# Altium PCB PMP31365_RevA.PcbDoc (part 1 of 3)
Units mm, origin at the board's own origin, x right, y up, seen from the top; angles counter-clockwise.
Board outline 134.61 x 49.53 mm, 4 copper layers (Top Layer, Layer 1, Layer 2, Bottom Layer), stack 1.787 mm thick; 183 components, 83 nets, 384 pads, 167 vias.
Unrouted connection lines stored in the file: 14.
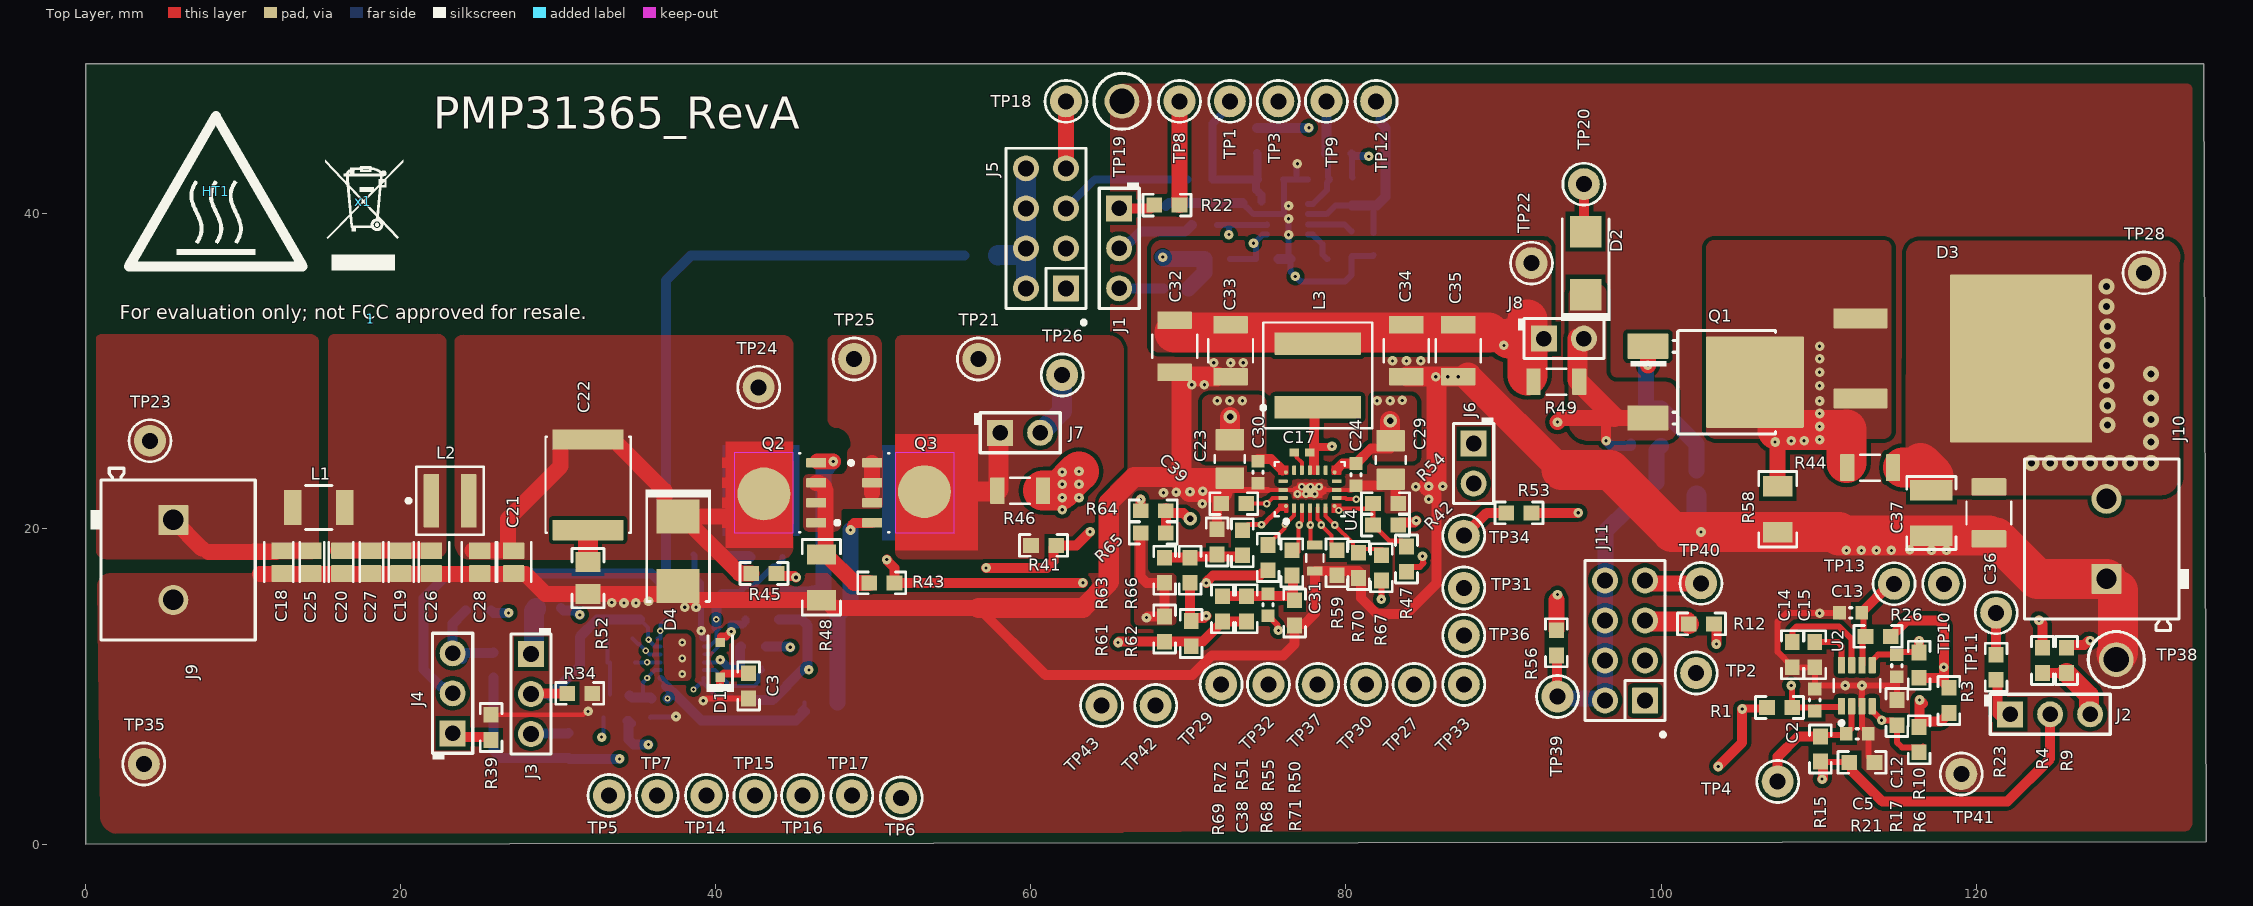
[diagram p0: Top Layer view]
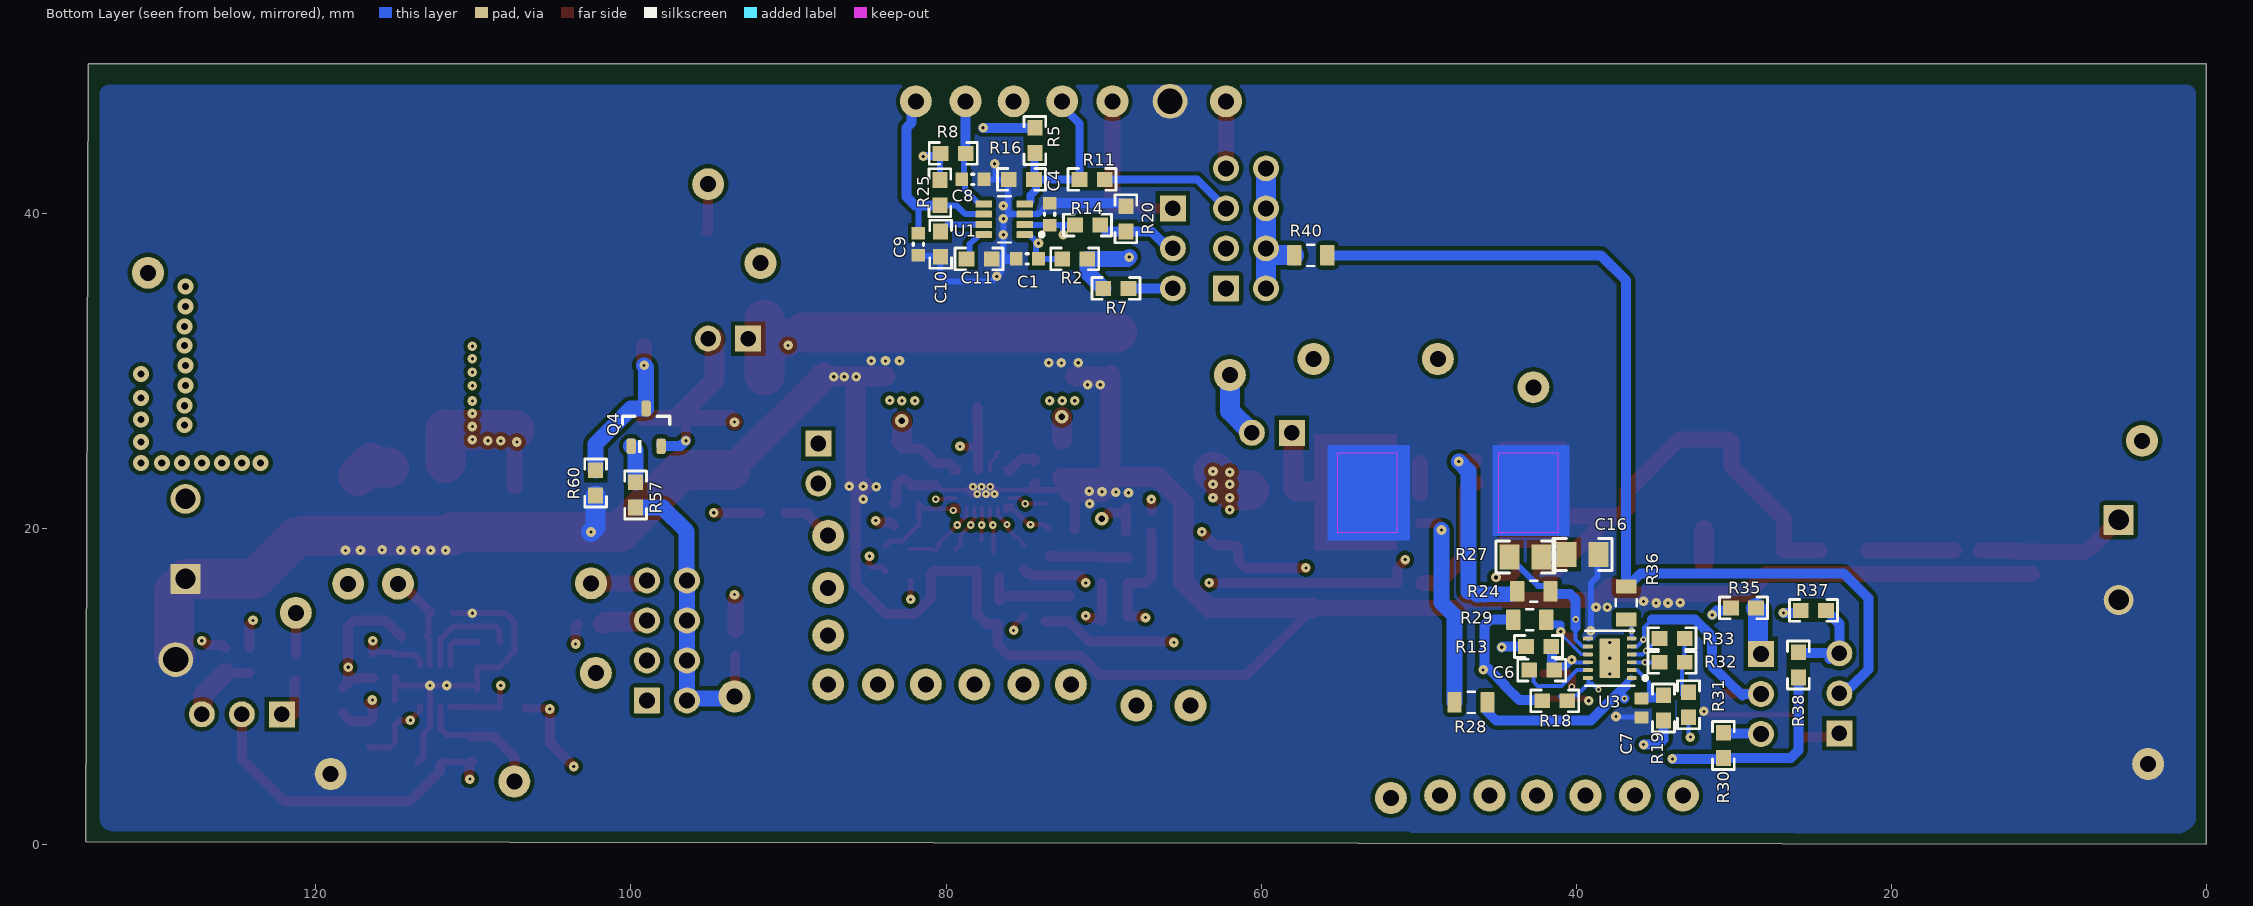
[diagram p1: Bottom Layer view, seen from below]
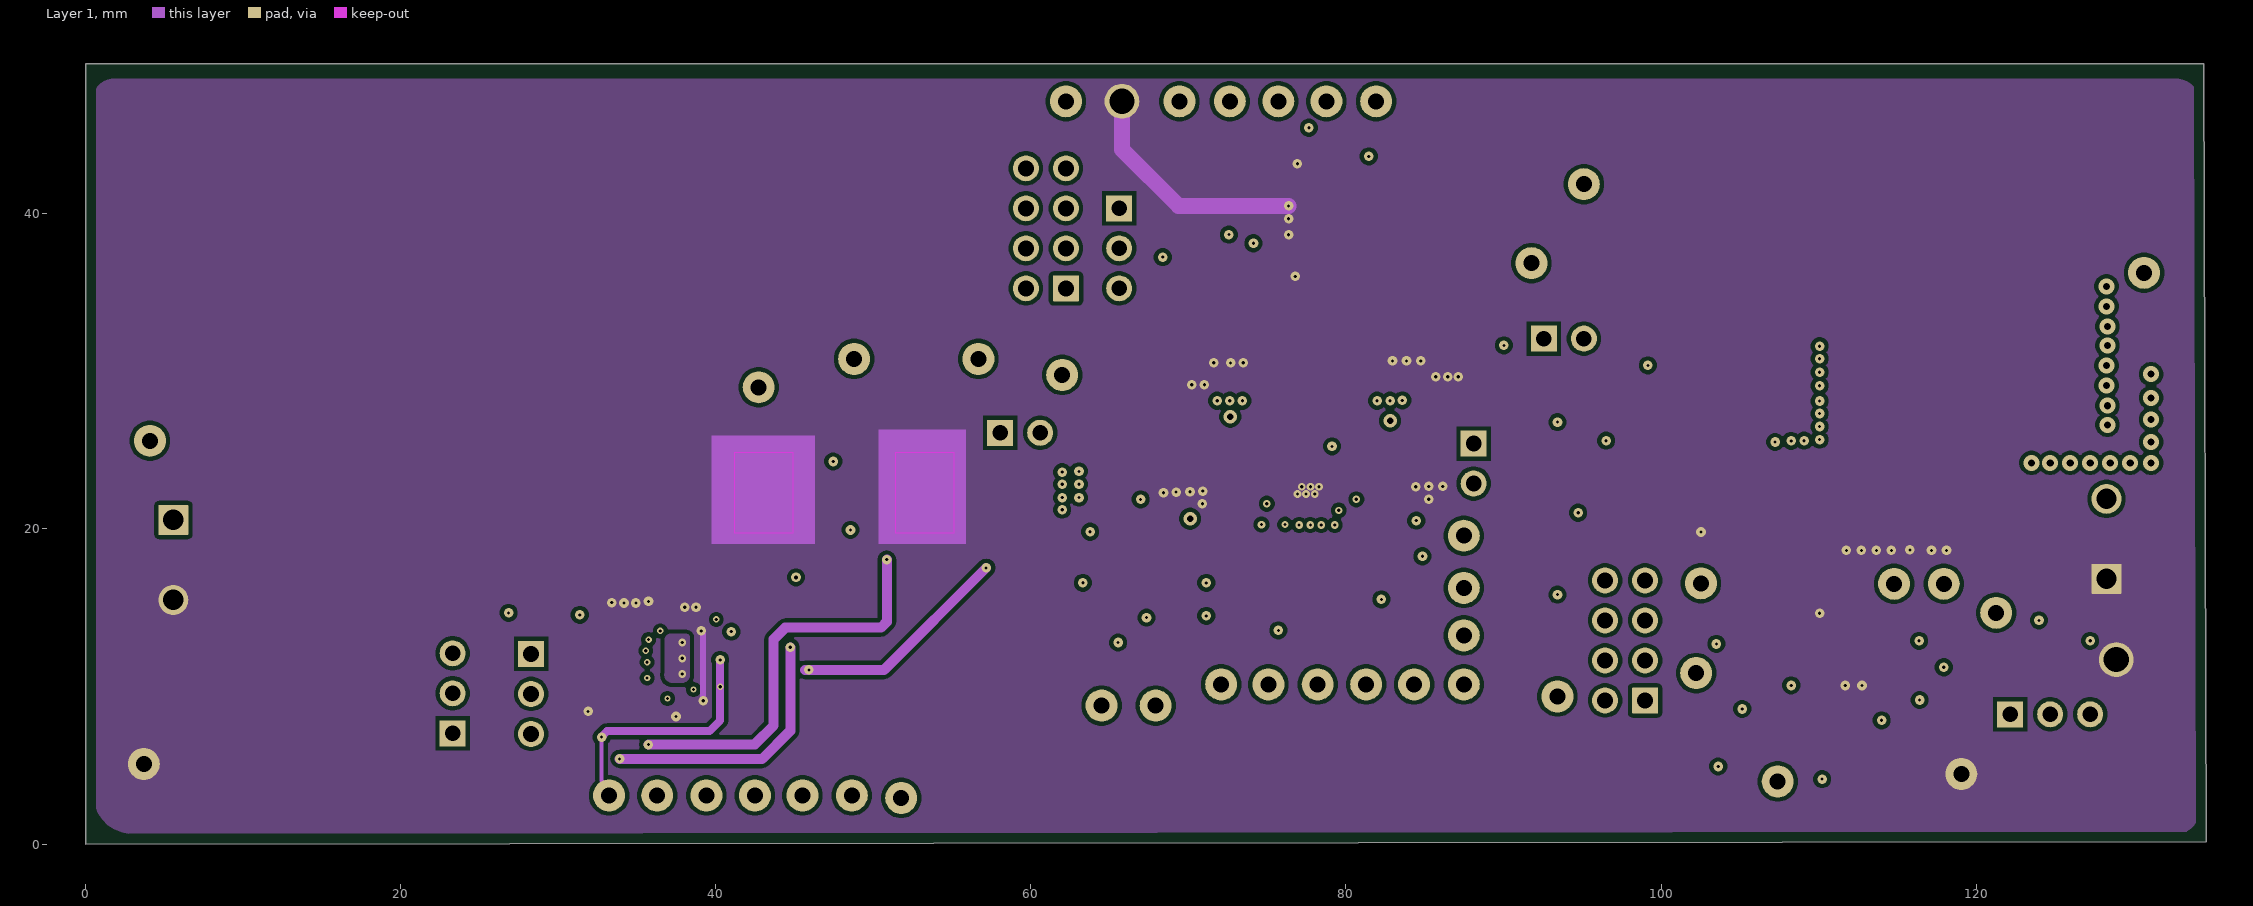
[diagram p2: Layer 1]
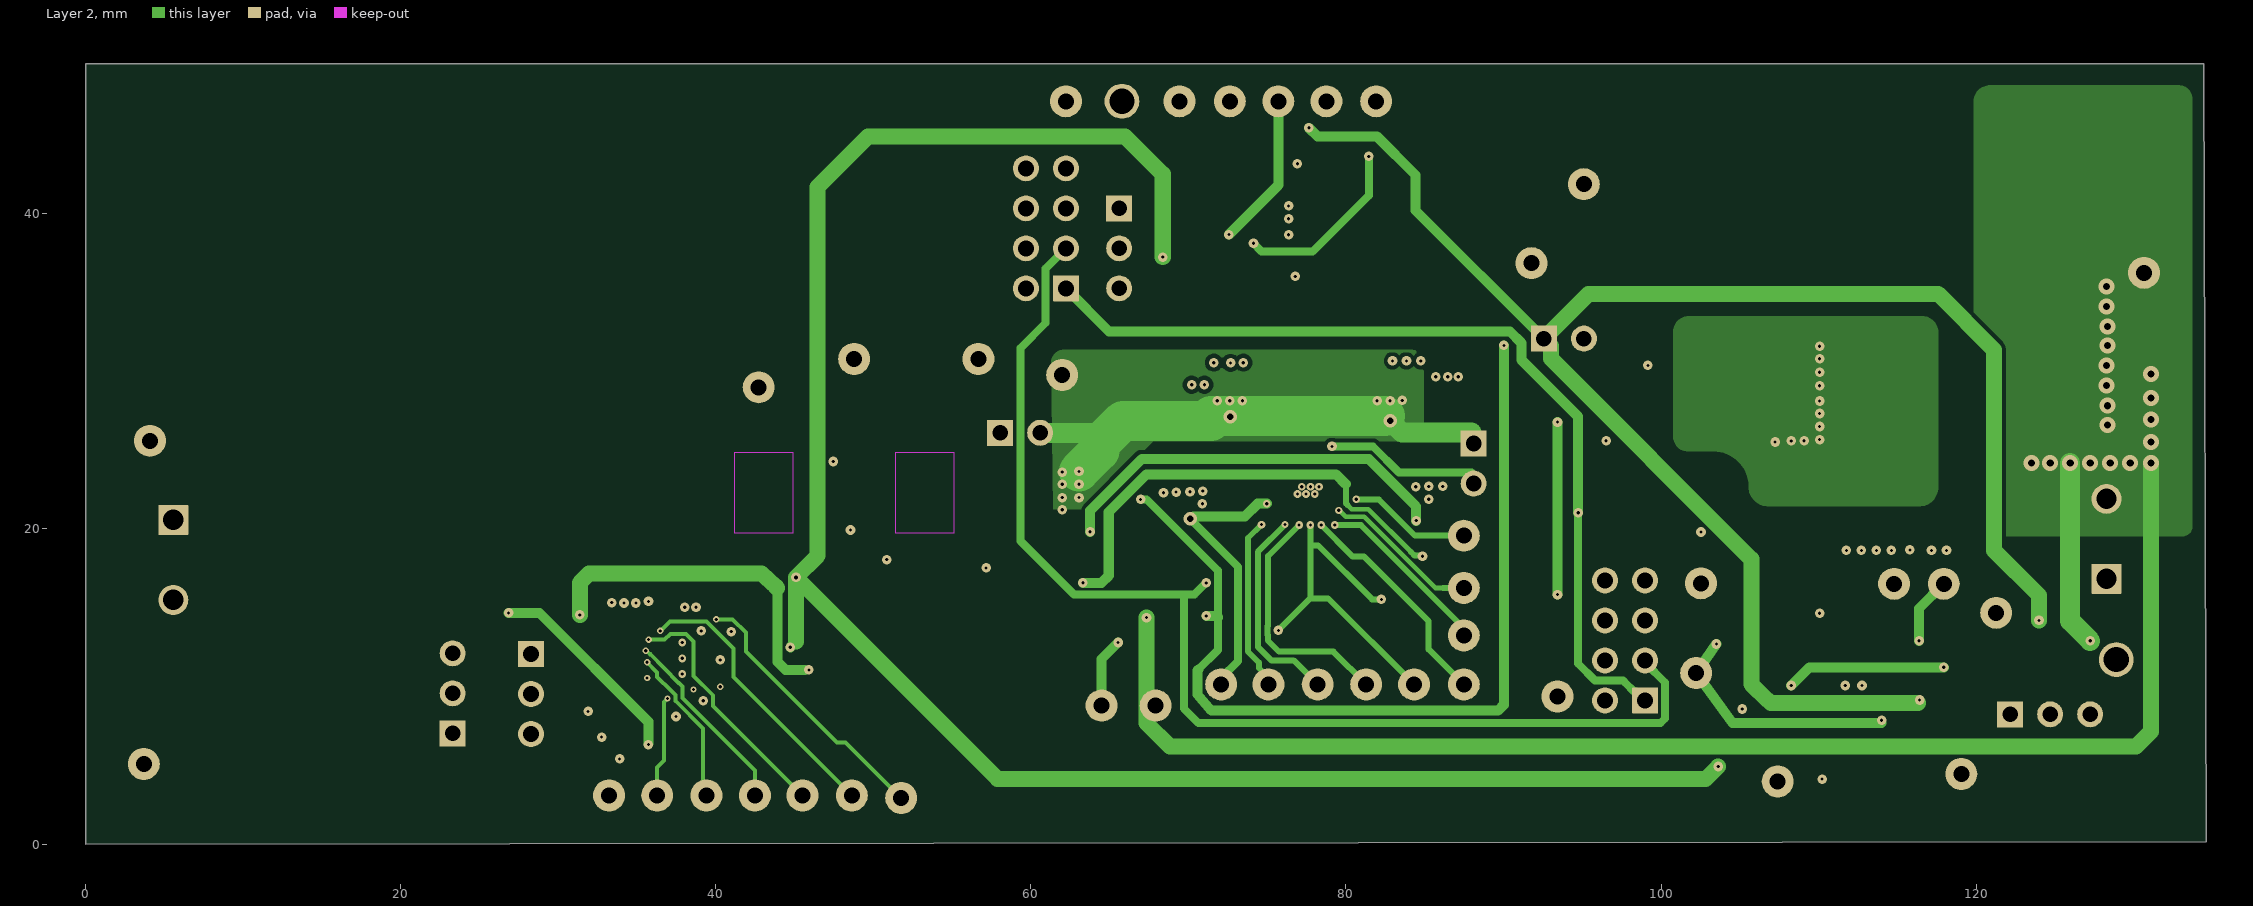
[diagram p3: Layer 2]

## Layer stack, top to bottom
Top Solder: solder mask 0.0102, Solder Resist, Dk 3.5
Top Layer: signal copper 0.0356
Dielectric 1: prepreg 0.0711, PP-006, Dk 4.1
Layer 1: signal copper 0.035
Dielectric1: core 1.5037, FR-4 High Tg, Dk 4.8
Layer 2: signal copper 0.035
Dielectric 2: prepreg 0.0711, PP-006, Dk 4.1
Bottom Layer: signal copper 0.0356
Bottom Solder: solder mask 0.0102, Solder Resist, Dk 3.5

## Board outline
0,0 0,49.53 134.461,49.53 134.611,0.143

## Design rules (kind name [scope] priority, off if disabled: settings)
AcuteAngle [All] p1: minimum=4.50000000000000E+0001 checktracksonly=FALSE
AssemblyTestPointUsage [All] p1: valid=2
BoardOutlineClearance BoardOutlineClearance_MountingHoles [OnCopper and InComponentClass('Mounting Holes')] p1: gap=1 ignorepadtopadclearanceinfootprint=FALSE
BoardOutlineClearance BoardOutlineClearance_Poly [OnCopper and IsPoly] p2: gap=0.635 ignorepadtopadclearanceinfootprint=FALSE
BoardOutlineClearance [OnCopper and Not InComponentClass('Logo') and not InComponentClass('FiducialMark') and not InRegion(1000,500,4000,800) and not InPoly] p3: gap=1.016 ignorepadtopadclearanceinfootprint=FALSE
Clearance Clearance_Keepouts [((IsTrack Or IsArc) And Not InPoly) And IsFree and IsKeepOut vs ((IsTrack Or IsArc) And Not InPoly) And IsFree and IsKeepOut] p1: gap=0 ignorepadtopadclearanceinfootprint=FALSE
Clearance Clearance_Poly [InPolygon] p2: gap=0.254 ignorepadtopadclearanceinfootprint=TRUE
Clearance Clearance_FiducialMark [IsKeepOut and InComponentClass('FiducialMark') vs IsPad and InComponentClass('FiducialMark')] p3: gap=0 ignorepadtopadclearanceinfootprint=FALSE
Clearance [All] p4: gap=0.178 ignorepadtopadclearanceinfootprint=TRUE
ComponentClearance ComponentClearance_MountingHoles_FiducialMarks [InComponentClass('Mounting Holes') vs InComponentClass('FiducialMark')] p1: gap=1.27 collisioncheckmode=3 verticalgap=0.254 showdistances=FALSE
ComponentClearance ComponentClearance_Shunt [InComponentClass('Header') vs InComponentClass('Shunt')] p2: gap=0 collisioncheckmode=3 verticalgap=0 showdistances=FALSE
ComponentClearance ComponentClearance_Logo [InComponentClass('Logo')] p3: gap=0.762 collisioncheckmode=3 verticalgap=0.254 showdistances=FALSE
ComponentClearance ComponentClearance_ScrewToNut [(HasFootprint('NY PMS 440 0025 PH')) vs (HasFootprint('Keystone_1902C'))] p4: gap=0.127 collisioncheckmode=3 verticalgap=0.254 showdistances=FALSE
ComponentClearance ComponentClearance_MountingHoles [InComponentClass('Mounting Holes')] p5: gap=2.54 collisioncheckmode=3 verticalgap=2540 showdistances=FALSE
ComponentClearance ComponentClearance_SmallPassives [HasFootprint('0201*') or HasFootprint('0402*') or HasFootprint('0508') or HasFootprint('0603*') or HasFootprint('0612') or HasFootprint('0805*') or HasFootprint('0815*') or HasFootprint('0830*') or HasFootprint('1206*') or HasFootprint('1210*') or HasFootprint('1808*') or HasFootprint('1812*') or HasFootprint('1825*') or HasFootprint('2010*') or HasFootprint('2220*') or HasFootprint('2225*') or HasFootprint('2512*') or HasFootprint('2728*') or HasFootprint('3518*') vs HasFootprint('0201*') or HasFootprint('0402*') or HasFootprint('0508') or HasFootprint('0603*') or HasFootprint('0612') or HasFootprint('0805*') or HasFootprint('0815*') or HasFootprint('0830*') or HasFootprint('1206*') or HasFootprint('1210*') or HasFootprint('1808*') or HasFootprint('1812*') or HasFootprint('1825*') or HasFootprint('2010*') or HasFootprint('2220*') or HasFootprint('2225*') or HasFootprint('2512*') or HasFootprint('2728*') or HasFootprint('3518*')] p6: gap=0.38 collisioncheckmode=3 verticalgap=0.254 showdistances=FALSE
ComponentClearance ComponentClearance_THtoSMT [IsThruComponent vs IsSMTComponent] p7: gap=0.762 collisioncheckmode=3 verticalgap=0.762 showdistances=FALSE
ComponentClearance ComponentClearance_THtoTH [IsThruComponent vs IsThruComponent] p8: gap=0.508 collisioncheckmode=3 verticalgap=0.762 showdistances=FALSE
ComponentClearance [All] p9: gap=0.508 collisioncheckmode=3 verticalgap=0.254 showdistances=FALSE
DiffPairsRouting [All] p1: maxlimit=2.54 minlimit=0.254 mostfreqgap=0.254 toplayer_minwidth=0.381 toplayer_maxwidth=0.381 toplayer_prefwidth=0.381 midlayer1_minwidth=0.381 midlayer1_maxwidth=0.381 midlayer1_prefwidth=0.381 midlayer2_minwidth=0.381 midlayer2_maxwidth=0.381 midlayer2_prefwidth=0.381 bottomlayer_minwidth=0.381 bottomlayer_maxwidth=0.381 bottomlayer_prefwidth=0.381 maxuncoupledlength=25.4
FabricationTestPointUsage TestPointUsage [All] p1: valid=2 allowmultiple=FALSE
FabricationTestpoint Testpoint [All] p1: side=3 testpointundercomponent=TRUE minsize=1.016 maxsize=2.54 preferedsize=1.524 minholesize=0 maxholesize=1.016 preferedholesize=0.813 testpointgrid=0.025 allowsidetop=TRUE allowsidebottom=TRUE usegrid=TRUE gridtolerance=0
FanoutControl Fanout_LCC [IsLCC] p1: bgadir=Out bgaviamode=Centered fanoutstyle=Auto fanoutdirection=Alternating viagrid=0.025 // Fanout_LCC (Default Rule)
FanoutControl Fanout_BGA [IsBGA] p2: bgadir=Out bgaviamode=Centered fanoutstyle=Auto fanoutdirection=Alternating viagrid=0.025 // Fanout_BGA (Default Rule)
FanoutControl Fanout_Default [All] p4: bgadir=Out bgaviamode=Centered fanoutstyle=Auto fanoutdirection=Alternating viagrid=0.025 // Fanout_Default (Default Rule)
FanoutControl Fanout_Small [(CompPinCount < 5)] p5: bgadir=Out bgaviamode=Centered fanoutstyle=Auto fanoutdirection=OutThenIn viagrid=0.025 // Fanout_Small (Default Rule)
HoleSize [All] p1: absolutevalues=TRUE maxlimit=6.375 minlimit=0.2 maxpercent=80.000 minpercent=20.000
MinimumAnnularRing MinimumAnnularRing_ThermalPadVias [IsVia and InAnyComponent] p1: minimumring=0.15
MinimumAnnularRing [All] p2: minimumring=0.099
MinimumSolderMaskSliver MinimumSolderMaskSliver_Logo [InComponentClass('Logo') vs InComponentClass('Logo')] p1: minsoldermaskwidth=0.018
MinimumSolderMaskSliver [All] p2: minsoldermaskwidth=0.027
PlaneConnect [All] p1: planeconnectstyle=Relief reliefexpansion=0.254 reliefentries=4 reliefconductorwidth=0.254 reliefairgap=0.254
PolygonConnect [All] p1: connectstyle=Direct reliefconductorwidth=0.254 reliefentries=4 polygonreliefangle="90 Angle" airgapwidth=0.254
RoutingVias ThermalPadVias [IsVia and InAnyComponent] p1: holewidth=0.2 width=0.5 viastyle="Through Hole" minholewidth=0.2 minwidth=0.5 maxholewidth=0.33 maxwidth=0.6
RoutingVias [All] p2: holewidth=0.406 width=0.864 viastyle="Through Hole" minholewidth=0.102 minwidth=0.127 maxholewidth=1.016 maxwidth=1.651
SilkToBoardRegionClearance [Not ((IsComment or IsDesignator) And (Hide <> 'False')) and not InRegion(1000,500,4000,800)] p1:
SilkToSilkClearance SilkToSilkClearance_Pb-FreeLogo [(HasFootprint('Pb-Free_Overlay_Medium') OR HasFootprint('Pb-Free_Overlay_Small')) vs (HasFootprint('Pb-Free_Overlay_Medium') OR HasFootprint('Pb-Free_Overlay_Small'))] p1 off: silktosilkclearance=0
SilkToSilkClearance [All] p2 off: silktosilkclearance=0.1
SilkToSolderMaskClearance SilkToComponentPadClearance [(IsPad or IsFill or IsRegion) and InAnycomponent] p1 off: minsilkscreentomaskgap=0.127 clearancetoexposedcopper=TRUE
SilkToSolderMaskClearance "Silk to Solder Mask Opening" [All] p2 off: minsilkscreentomaskgap=0.1 clearancetoexposedcopper=FALSE
SolderMaskExpansion [All] p1: expansion=0.05 istentingtop=FALSE
UnRoutedNet [All] p1: checkbadconnections=TRUE
Width [All] p1: maxlimit=2.54 minlimit=0.152 preferedwidth=0.254 checkconnectedcopper=TRUE
14 further rules are at their usual default settings.

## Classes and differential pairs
component class Header: J1 J2 J3 J4 J5 J6 J7 J8 J11

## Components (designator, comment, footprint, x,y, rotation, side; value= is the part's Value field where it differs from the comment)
1 "FCC disclaimer" FCC_disclaimer 18.098,33.337 r0 top
C1 "HMK107B7104KAHT" 0603L 74.833,37.148 r0 bottom value=0.1uF
C2 "HMK107B7104KAHT" 0603L 109.761,9.142 r90 top value=0.1uF
C3 "GRM188R72A104KA35D" 0603 42.081,10.037 r270 top value=0.1uF
C4 "HMK107B7104KAHT" 0603L 73.427,39.983 r90 bottom value=0.1uF
C5 "HMK107B7104KAHT" 0603L 112.469,6.987 r0 top value=0.1uF
C6 "06035C104KAZ2A" 0603 42.183,11.036 r0 bottom value=0.1uF
C7 "C0603C153K5RACTU" FP-C0603C153K5RACTU_0603-MFG 35.848,8.638 r270 bottom
C8 "HMK107B7104KAHT" 0603L 78.292,42.198 r180 bottom value=0.1uF
C9 "HMK107B7104KAHT" 0603L 81.755,38.078 r270 bottom value=0.1uF
C10 "C0603C104K5RACTU" 0603 80.339,38.078 r270 bottom value=0.1uF
C11 "C0603C104K5RACTU" 0603 77.902,37.148 r180 bottom value=0.1uF
C12 "HMK107B7104KAHT" 0603L 114.973,11.32 r270 top value=0.1uF
C13 "HMK107B7104KAHT" 0603L 112.034,14.677 r180 top value=0.1uF
C14 "C0603C104K5RACTU" 0603 108.332,12.02 r270 top value=0.1uF
C15 "C0603C104K5RACTU" 0603 109.761,12.02 r270 top value=0.1uF
C16 "08051C103JAT2A" 0805_HV 39.594,18.381 r180 bottom value=0.01uF
C17 "Cboot" 0402L 77.207,24.853 r180 top value=0.1uF
C18 "GRM21BD72A225ME01K" FP-GRM21BD72A225ME01K_0805-IPC_C 12.454,17.899 r90 top value=2.2µF
C19 "GRM21BD72A225ME01K" FP-GRM21BD72A225ME01K_0805-IPC_C 20.002,17.899 r90 top value=2.2µF
C20 "GRM21BD72A225ME01K" FP-GRM21BD72A225ME01K_0805-IPC_C 16.255,17.899 r90 top value=2.2µF
C21 "GRM21BD72A225ME01K" FP-GRM21BD72A225ME01K_0805-IPC_C 27.157,17.899 r90 top value=2.2µF
C22 "CGA9P3X7R1H226M250KB" FP-CGA9P3X7R1H226M250KB_2220-MFG 31.885,22.805 r90 top value=22µF
C23 "GRM31CC72A475KE11L" FP-GRM31CC72A475KE11L_1206-IPC_C 72.627,24.447 r90 top value=4.7µF
C24 "HMK107B7104KAHT" 0603L 80.635,23.453 r270 top value=0.1uF
C25 "GRM21BD72A225ME01K" FP-GRM21BD72A225ME01K_0805-IPC_C 14.287,17.899 r90 top value=2.2µF
C26 "GRM21BD72A225ME01K" FP-GRM21BD72A225ME01K_0805-IPC_C 21.937,17.899 r90 top value=2.2µF
C27 "GRM21BD72A225ME01K" FP-GRM21BD72A225ME01K_0805-IPC_C 18.098,17.899 r90 top value=2.2µF
C28 "GRM21BD72A225ME01K" FP-GRM21BD72A225ME01K_0805-IPC_C 25,17.899 r90 top value=2.2µF
C29 "GRM31CC72A475KE11L" FP-GRM31CC72A475KE11L_1206-IPC_C 82.841,24.379 r90 top value=4.7µF
C30 "HMK107B7104KAHT" 0603L 74.413,23.596 r270 top value=0.1uF
C31 "CVCC" FP-CGA3E1X7R1C105M080AC_0603-IPC_C 78.023,18.154 r90 top value=1µF
C32 "C3225X7R2A106K250AC" FP-C3225X7R2A106K250AC_1210-MFG 69.124,31.601 r90 top value=10µF
C33 "C3225X7R2A106K250AC" FP-C3225X7R2A106K250AC_1210-MFG 72.677,31.314 r90 top value=10µF
C34 "C3225X7R2A106K250AC" FP-C3225X7R2A106K250AC_1210-MFG 83.828,31.314 r90 top value=10µF
C35 "C3225X7R2A106K250AC" FP-C3225X7R2A106K250AC_1210-MFG 87.13,31.314 r90 top value=DNP
C36 "C3225X7R2A106K250AC" FP-C3225X7R2A106K250AC_1210-MFG 120.821,21.02 r90 top value=10µF
C37 "Used in BOM report" 1210 117.169,21.02 r270 top
C38 "C0603C100J5GACTU" 0603 73.675,14.931 r90 top value=10pF
C39 "C0603C100J5GACTU" 0603 72.875,21.604 r180 top value=10pF
D1 "1N4148WS-7-F" SOD-323 40.273,11.691 r90 top value=75V
D2 "TBD" SMA 95.215,36.875 r90 top
D3 "MBRB41H100CTT4G" DDPAK 118.916,30.826 r0 top value=100V
D4 "1SMB5946BT3G" SMB 37.6,18.578 r270 top value=75V
HT1 "CAUTION HOT SURFACE" IEC_HotSurface_Medium 8.255,41.434 r0 top
J1 "5-146278-3" TE_5-146278-3 65.602,37.815 r270 top
J2 "5-146278-3" TE_5-146278-3 124.706,8.234 r0 top
J3 "5-146278-3" TE_5-146278-3 28.269,9.523 r270 top
J4 "5-146278-3" TE_5-146278-3 23.288,9.566 r90 top
J5 "TSW-104-07-G-D" TSW-104-07-G-D 60.954,39.085 r90 top
J6 "5-146278-2" TE_5-146278-2 88.106,24.153 r270 top
J7 "5-146278-2" TE_5-146278-2 59.317,26.107 r0 top
J8 "5-146278-2" TE_5-146278-2 93.833,32.083 r0 top
J9 "1715721" PhoenixContact_1715721 5.556,18.032 r270 top
J10 "1715721" PhoenixContact_1715721 128.282,19.37 r90 top
J11 "TSW-104-07-G-D" TSW-104-07-G-D 97.721,12.924 r90 top
L1 "FBMH3225HM601NT" 1210_280 14.797,21.359 r0 top value="600 ohm"
L2 "XGL4030-152MEC" FP-XGL4030-152MEC_SMT2_4MM0_4MM0-MFG 23.122,21.789 r0 top value=1.5uH
L3 "XGL6060-222MEC" FP-XGL6060-182MEC_SMT2_6MM51_6MM71-MFG 78.207,29.749 r90 top value=2.2uH
Q1 "SPD15P10PLGBTMA1" DPAK 102.564,29.323 r0 top value=-100V
Q2 "NTMFS08N004C" FP-NTMFS08N004C_PQFN8-MFG 43.696,22.297 r90 top
Q3 "NTMFS08N004C" FP-NTMFS08N004C_PQFN8-MFG 52.589,22.297 r270 top
Q4 "BSS63" SOT-23 99.042,26.452 r90 bottom value="100 V"
R1 "RMCF0603ZT0R00" 0603 107.532,8.665 r0 top value=0
R2 "RMCF0603ZT0R00" 0603 71.827,37.148 r0 bottom value=0
R3 "RMCF0603ZT0R00" 0603 118.269,9.114 r90 top value=0
R4 "RMCF0603ZT0R00" 0603 124.21,11.654 r270 top value=TBD
R5 "RMCF0603ZT0R00" 0603 74.362,44.669 r90 bottom value=DNP
R6 "RMCF0603ZT0R00" 0603 116.386,6.623 r90 top value=DNP
R7 "RMCF0603ZT0R00" 0603 69.216,35.275 r180 bottom value=TBD
R8 "CRCW060310K0FKEA" 0603 79.545,43.842 r0 bottom value=10.0k
R9 "RMCF0603ZT0R00" 0603 125.742,11.654 r270 top value=TBD
R10 "CRCW060310K0FKEA" 0603 116.386,11.35 r270 top value=10.0k
R11 "RMCF0603ZT0R00" 0603 70.729,42.198 r0 bottom value=0
R12 "RMCF0603ZT0R00" 0603 102.564,13.971 r0 top value=0
R13 "CRCW060310K0FKEA" 0603 42.38,12.536 r0 bottom value=10.0k
R14 "RMCF0603ZT0R00" 0603 71.014,39.283 r180 bottom value=0
R15 "RMCF0603ZT0R00" 0603 110.115,6.032 r270 top value=0
R16 "RMCF0603ZT0R00" 0603 75.217,42.198 r180 bottom value=DNP
R17 "RMCF0603ZT0R00" 0603 114.973,8.342 r270 top value=DNP
R18 "RMCF0603ZT0R00" 0603 41.356,9.095 r0 bottom value=0
R19 "RMCF0603ZT0R00" 0603 34.453,8.638 r270 bottom value=0
R20 "RMCF0603ZT0R00" 0603 68.58,39.688 r90 bottom value=TBD
R21 "RMCF0603ZT0R00" 0603 112.758,5.179 r0 top value=TBD
R22 "RMCF0603ZT0R00" 0603 68.63,40.562 r0 top value=0
R23 "RMCF0603ZT0R00" 0603 121.28,11.22 r90 top value=0
R24 "RMCF0805ZT0R00" FP-RMCF0805ZT0R00_0805-MFG 42.682,16.044 r180 bottom
R25 "CRCW060310K0FKEA" 0603 80.387,41.348 r90 bottom value=10.0k
R26 "CRCW060310K0FKEA" 0603 113.778,13.176 r0 top value=10.0k
R27 "CRCW0805100RFKEA" 0805_HV 43.214,18.214 r0 bottom value=100
R28 "RMCF0805ZT0R00" FP-RMCF0805ZT0R00_0805-MFG 46.67,8.988 r0 bottom
R29 "RMCF0805ZT0R00" FP-RMCF0805ZT0R00_0805-MFG 42.943,14.239 r180 bottom
R30 "CRCW0603100KFKEA" 0603 30.651,6.257 r90 bottom value=100k
R31 "RMCF0603ZT0R00" 0603 32.865,8.841 r90 bottom value=0
R32 "RMCF0603ZT0R00" 0603 33.905,11.538 r0 bottom value=0
R33 "RMCF0603ZT0R00" 0603 33.905,13.038 r0 bottom value=0
R34 "CRCW06033K48FKEA" 0603 31.359,9.566 r180 top value=3.48k
R35 "CRCW0603100KFKEA" 0603 29.374,14.988 r0 bottom value=100k
R36 "RMCF0805ZT0R00" FP-RMCF0805ZT0R00_0805-MFG 36.816,15.307 r90 bottom
R37 "RMCF0603ZT0R00" 0603 24.936,14.83 r0 bottom value=DNP
R38 "RMCF0603ZT0R00" 0603 25.893,11.366 r270 bottom value=0
R39 "RMCF0603ZT0R00" 0603 25.729,7.4 r270 top value=0
R40 "RMCF0805ZT0R00" FP-RMCF0805ZT0R00_0805-MFG 56.844,37.372 r0 bottom
R41 "RMCF0603ZT0R00" 0603 60.801,18.954 r0 top value=0
R42 "CRCW0603100KFKEA" 0603 82.514,20.254 r0 top value=100k
R43 "RMCF0603ZT0R00" 0603 50.535,16.579 r0 top value=0
R44 "CRCW12060000Z0EAC" FP-CRCW12060000Z0EAC_1206-MFG 113.274,23.897 r0 top value=0
R45 "RMCF0603ZT0R00" 0603 43.046,17.173 r0 top value=0
R46 "CRCW12060000Z0EAC" FP-CRCW12060000Z0EAC_1206-MFG 59.317,22.429 r0 top value=0
R47 "RMCF0603ZT0R00" 0603 83.841,18.091 r270 top value=DNP
R48 "RC1206FR-0747KL" 1206 46.696,16.929 r90 top value=47.0k
R49 "CRCW12060000Z0EAC" FP-CRCW12060000Z0EAC_1206-MFG 93.357,29.353 r0 top value=0
R50 "RMCF0603ZT0R00" 0603 76.562,17.851 r90 top value=0
R51 "RMCF0603ZT0R00" 0603 73.427,19.126 r90 top value=0
R52 "ESR10EZPJ1R0" 0805_HV 31.885,16.883 r90 top value=1.0
R53 "RMCF0603ZT0R00" 0603 90.976,21.028 r180 top value=0
R54 "RMCF0603ZT0R00" 0603 82.514,21.604 r180 top value=DNP
R55 "RMCF0603ZT0R00" 0603 75.057,18.179 r90 top value=0
R56 "CRCW060320K0FKEA" 0603 93.357,12.772 r90 top value=20.0k
R57 "CRCW06031K00FKEA" 0603 99.707,22.16 r90 bottom value=1.00k
R58 "CRCW120610K0JNEA" 1206 107.411,21.256 r90 top value=10k
R59 "" 0603 79.432,17.854 r270 top value=150k
R60 "CRCW060310K0FKEA" 0603 102.247,22.925 r90 bottom value=10.0k
R61 "M55342K12B49D9T" 0603 68.491,13.641 r90 top value=49.9
R62 "RMCF0603ZT0R00" 0603 70.178,13.357 r90 top value=DNP
R63 "RMCF0603ZT0R00" 0603 68.491,17.379 r270 top value=DNP
R64 "RMCF0603ZT0R00" 0603 67.766,21.155 r0 top value=0
R65 "RMCF0603ZT0R00" 0603 67.766,19.747 r180 top value=DNP
R66 "CRCW06034K99FKEA" 0603 70.105,17.379 r270 top value=4.99k
R67 "RMCF0603ZT0R00" 0603 82.246,17.534 r270 top value=DNP
R68 "5V" 0603L 75.051,15.185 r90 top value=0
R69 "RMCF0603ZT0R00" 0603 72.16,14.931 r270 top value=DNP
R70 "CRCW060315K8FKEA" 0603 80.785,17.687 r90 top value=15.8k
R71 "RMCF0603ZT0R00" 0603 76.747,14.671 r90 top value=DNP
R72 "RMCF0603ZT0R00" 0603 71.827,19.179 r270 top value=DNP
TP1 "5003" Keystone5003 72.627,47.149 r180 top
TP2 "5003" Keystone5003 102.235,10.854 r180 top
TP3 "5003" Keystone5003 75.707,47.149 r180 top
TP4 "5003" Keystone5003 107.411,3.969 r180 top
TP5 "5004" Keystone5004 33.218,3.082 r90 top
TP6 "5004" Keystone5004 51.764,2.923 r270 top
TP7 "5004" Keystone5004 36.276,3.082 r180 top
TP8 "5003" Keystone5003 69.43,47.149 r180 top
TP9 "5003" Keystone5003 78.757,47.149 r180 top
TP10 "5003" Keystone5003 117.951,16.519 r180 top
TP11 "5003" Keystone5003 121.28,14.677 r180 top
TP12 "5003" Keystone5003 81.915,47.149 r180 top
TP13 "5003" Keystone5003 114.797,16.519 r180 top
TP14 "5004" Keystone5004 39.4,3.082 r180 top
TP15 "5004" Keystone5004 42.478,3.082 r0 top
TP16 "5004" Keystone5004 45.498,3.082 r0 top
TP17 "5004" Keystone5004 48.629,3.082 r0 top
TP18 "5004" Keystone5004 62.224,47.149 r270 top
TP19 "GND" Keystone5011 65.778,47.149 r180 top
TP20 "5000" Keystone5000 95.103,41.888 r90 top
TP21 "5000" Keystone5000 56.667,30.792 r90 top
TP22 "5000" Keystone5000 91.776,36.875 r90 top
TP23 "5000" Keystone5000 4.072,25.599 r90 top
TP24 "5000" Keystone5000 42.716,28.996 r90 top
TP25 "5000" Keystone5000 48.776,30.792 r90 top
TP26 "5000" Keystone5000 61.984,29.776 r90 top
TP27 "5000" Keystone5000 84.326,10.13 r90 top
TP28 "5000" Keystone5000 130.663,36.26 r90 top
TP29 "5000" Keystone5000 72.075,10.13 r90 top
TP30 "5000" Keystone5000 81.282,10.13 r90 top
TP31 "5000" Keystone5000 87.483,16.258 r90 top
TP32 "5000" Keystone5000 75.076,10.13 r90 top
TP33 "5000" Keystone5000 87.483,10.13 r90 top
TP34 "5000" Keystone5000 87.483,19.57 r90 top
TP35 "5001" Keystone5001 3.683,5.08 r90 top
TP36 "5000" Keystone5000 87.483,13.242 r90 top
TP37 "5000" Keystone5000 78.207,10.13 r90 top
TP38 "GND" Keystone5011 128.905,11.706 r0 top
TP39 "5000" Keystone5000 93.427,9.367 r90 top
TP40 "5000" Keystone5000 102.536,16.547 r90 top
TP41 "5001" Keystone5001 119.062,4.445 r90 top
TP42 "5000" Keystone5000 67.919,8.788 r90 top
TP43 "5000" Keystone5000 64.486,8.788 r90 top
U1 "TPS3762-Q1" DDF0008A-MFG 76.302,39.658 r0 bottom
U2 "TPS3762-Q1" DDF0008A-MFG 112.433,10.05 r90 top
U3 "LM74800" DRR0012E-MFG 37.862,11.788 r0 bottom
U4 "LM68645SCRZTRQ1" RZT0020A-MFG 77.707,22.528 r90 top
x1 "WEEE logo" WEEE_Minimum 17.621,40.799 r0 top

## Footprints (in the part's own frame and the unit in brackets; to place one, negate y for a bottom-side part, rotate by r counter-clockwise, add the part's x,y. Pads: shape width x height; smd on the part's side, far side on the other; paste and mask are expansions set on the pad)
0402L [mm] "0402 from SM-752 data"
  rect 0.6x0.5 smd: 1(-0.5,0) 2(0.5,0)
  body extent -0.55,-0.3 0.55,0.3, height 0.6
0603 [mm] "0603 from SM-752 data"
  rect 1x0.95 smd: 1(-0.8,0) 2(0.8,0)
  silkscreen extent -1.52,-0.69 1.52,0.69, body extent -0.87,-0.47 0.87,0.47, height 1
0603L [mm] "0603 from SM-752 data"
  rect 0.8x0.85 smd: 1(-0.7,0) 2(0.7,0)
  silkscreen extent -0.07,-0.33 0.07,0.33, body extent -0.87,-0.47 0.87,0.47, height 1
0805_HV [mil] "0805 with 30mil clearance between pads"
  rect 50x63 smd: 1(-40,0) 2(40,0)
  silkscreen extent -74,-40 74,40, body extent -43,-29 43,29, height 57
1206 [mm] "1206 from SM-752 data"
  rect 1.3x1.85 smd: 1(-1.45,0) 2(1.45,0)
  silkscreen extent -2.4,-1.21 2.4,1.21, body extent -1.7,-0.9 1.7,0.9, height 1.35
1210 [mm] "1210 from SM-752 data"
  rect 1.3x2.7 smd: 1(-1.45,0) 2(1.45,0)
  silkscreen extent -2.32,-1.57 2.32,1.57, body extent -1.7,-1.35 1.7,1.35, height 1.35
1210_280 [mm] "SMD, 2-Leads, Body 3.6x2.8mm, Height 2.8mm"
  rect 1.1x2.2 smd: 1(-1.65,0) 2(1.65,0)
  silkscreen extent -0.84,-1.4 0.84,1.4, body extent -1.8,-1.4 1.8,1.4, height 2.8
DDF0008A-MFG [mm]
  rrect22% 1.05x0.45 smd paste+0 mask+0: 1(-1.3,0.975) 2(-1.3,0.325) 3(-1.3,-0.325) 4(-1.3,-0.975) 5(1.3,-0.975) 6(1.3,-0.325) 7(1.3,0.325) 8(1.3,0.975)
  silkscreen extent -2.5,-1.48 0.4,1.48, body extent -1.41,-1.45 1.41,1.45, height 1.1
DDPAK [mil] "D2-PAK, 3-Pads, Body 9.7x10.4mm (max), TO-263AB, using Vishay Silionix recommended pad sizes"
  rrect8% 135x49.49 smd: 1(-246.06,100) 3(-246.06,-100)
  rrect1% 355x420 smd paste-181.1: 2(155.51,0)
  body extent -295,-202 324,202, height 180
DPAK [mm] "D-PAK, 3-Pads, Body 6.22x6.73mm (max), TO-252AA using nominal STEP model"
  rrect6% 2.6x1.6 smd: 1(-3.4,2.28) 3(-3.4,-2.28)
  rrect2% 6.2x5.8 smd paste-2.9: 4(3.4,0)
  silkscreen extent -4.5,-3.3 4.7,3.28, body extent -3.86,-3.29 5.84,3.29, height 2.48
DRR0012E-MFG [mm]
  rrect40% 0.62x0.25 smd paste+0 mask+0: 1(-1.39,1.25) 2(-1.39,0.75) 3(-1.39,0.25) 4(-1.39,-0.25) 5(-1.39,-0.75) 6(-1.39,-1.25) 7(1.39,-1.25) 8(1.39,-0.75) 9(1.39,-0.25) 10(1.39,0.25) 11(1.39,0.75) 12(1.39,1.25)
  rrect8% 1.3x2.5 smd paste-1000 mask+0: 13(0,0)
  silkscreen extent -2.37,-1.75 1.55,1.75, body extent -1.5,-1.5 1.5,1.5, height 0.8
FCC_disclaimer [mm]
FP-C0603C153K5RACTU_0603-MFG [mm]
  rrect13% 0.75x0.9 smd paste+0 mask+0: 1(-0.6,0) 2(0.6,0)
  body extent -0.8,-0.4 0.8,0.4, height 0.87
FP-C3225X7R2A106K250AC_1210-MFG [mm]
  rrect9% 1.1x2.2 smd paste+0 mask+0: 1(-1.65,0) 2(1.65,0)
  silkscreen extent -0.72,-1.43 0.72,1.43, body extent -2.3,-1.53 2.3,1.53, height 0.25
FP-CGA3E1X7R1C105M080AC_0603-IPC_C [mm]
  rrect18% 0.556x1.006 smd paste+0 mask+0: 1(-0.825,0) 2(0.825,0)
  silkscreen extent -0.25,-0.55 0.25,0.55, body extent -1.2,-0.65 1.2,0.65, height 0.25
FP-CGA9P3X7R1H226M250KB_2220-MFG [mm]
  rrect8% 1.3x4.5 smd paste+0 mask+0: 1(-2.875,0) 2(2.875,0)
  silkscreen extent -3.05,-2.7 3.05,2.7, body extent -3.62,-2.8 3.62,2.8, height 0.25
FP-CRCW12060000Z0EAC_1206-MFG [mm]
  rrect11% 0.9x1.7 smd paste+0 mask+0: 1(-1.45,0) 2(1.45,0)
  silkscreen extent -0.63,-0.82 0.63,0.82, body extent -2,-0.95 2,0.95, height 0.25
FP-GRM21BD72A225ME01K_0805-IPC_C [mm]
  rrect9% 1.055x1.356 smd paste+0 mask+0: 1(-0.726,0) 2(0.726,0)
  silkscreen extent -1.25,-1.12 1.25,1.12, body extent -1.35,-0.82 1.35,0.82, height 0.25
FP-GRM31CC72A475KE11L_1206-IPC_C [mm]
  rrect7% 1.353x1.804 smd paste+0 mask+0: 1(-1.225,0) 2(1.225,0)
  silkscreen extent -0.25,-0.95 0.25,0.95, body extent -2,-1.05 2,1.05, height 0.25
FP-NTMFS08N004C_PQFN8-MFG [mm]
  rrect16% 0.61x1.27 smd paste+0 mask+0: 1(-1.905,-2.67) 2(-0.635,-2.67) 3(0.635,-2.67) 4(1.905,-2.67)
  round 3.356 smd paste+0 mask+0: 5-6-7-8(-0.069,0.65)
  Top Layer region: -2.21,3.305 -1.6,3.305 -1.6,2.535 -0.94,2.535 -0.94,3.305 -0.33,3.305 -0.33,2.535 0.33,2.535 0.33,3.305 0.94,3.305 0.94,2.535 1.6,2.535 1.6,3.305 2.21,3.305 2.21,2.035 1.955,2.035 1.955,-1.215 -1.955,-1.215 -1.955,2.035 -2.21,2.035 -2.21,3.305
  Keep-Out Layer region: -2.55,-1.215 2.55,-1.215 2.55,2.535 -2.55,2.535
  silkscreen extent -2.5,-4.14 2.5,-1.59, body extent -2.65,-3.4 2.65,3.4, height 0.25
FP-RMCF0805ZT0R00_0805-MFG [mm]
  rrect11% 0.9x1.3 smd paste+0 mask+0: 1(-1.05,0) 2(1.05,0)
  silkscreen extent -0.23,-0.67 0.23,0.67, body extent -1,-0.63 1,0.63, height 0.65
FP-XGL4030-152MEC_SMT2_4MM0_4MM0-MFG [mm]
  rrect10% 0.98x3.4 smd paste+0 mask+0: 1(-1.185,0) 2(1.185,0)
  silkscreen extent -2.75,-2.15 2.15,2.15, body extent -2.25,-2.25 2.25,2.25, height 0.25
FP-XGL6060-182MEC_SMT2_6MM51_6MM71-MFG [mm]
  rrect7% 1.43x5.5 smd paste+0 mask+0: 1(-2.02,0) 2(2.02,0)
  silkscreen extent -3.35,-3.45 3.35,3.58, body extent -3.45,-3.55 3.45,3.55, height 0.25
IEC_HotSurface_Medium [mm]
  silkscreen extent -5.51,-4.76 5.51,4.78
Keystone5000 [mil] "For Keystone 500x miniature loop terminals"
  round 80 hole 40: 1(0,0)
  silkscreen extent -52,-52 52,52, body extent -49,-49 49,49, height 182
Keystone5001 [mil] "For Keystone 500x miniature loop terminals"
  round 80 hole 40: 1(0,0)
  silkscreen extent -52,-52 52,52, body extent -49,-49 49,49, height 182
Keystone5003 [mil] "For Keystone 500x miniature loop terminals"
  round 80 hole 40: 1(0,0)
  silkscreen extent -52,-52 52,52, body extent -49,-49 49,49, height 182
Keystone5004 [mil] "For Keystone 500x miniature loop terminals"
  round 80 hole 40: 1(0,0)
  silkscreen extent -52,-52 52,52, body extent -49,-49 49,49, height 182
Keystone5011 [mil] "Keystone Multipurpose loops"
  round 87 hole 63: 1(0,0)
  silkscreen extent -70,-70 70,70, body extent -63,-63 62,62, height 319
PhoenixContact_1715721 [mm] "Phoenix Contact 1715721 used on LM3445 design from Longmont"
  rrect5% 1.905x1.905 hole 1.3: 1(-2.54,0)
  round 1.9 hole 1.3: 2(2.54,0)
  silkscreen extent -5.82,-5.25 5.08,5.2, body extent -5.82,-4.6 5.08,5.2, height 14.2
RZT0020A-MFG [mm]
  round 0.259 smd paste+0 mask+0: 1(-1.069,1.519) 7(-1.069,-1.569) 11(1.069,-1.569) 17(1.069,1.519)
  rrect40% 0.6x0.25 smd paste+0 mask+0: 2(-1.2,1) 3(-1.2,0.5) 4(-1.2,0) 5(-1.2,-0.5) 6(-1.2,-1) 12(1.2,-1) 13(1.2,-0.5) 14(1.2,0) 15(1.2,0.5) 16(1.2,1)
  rrect40% 0.25x0.6 smd paste+0 mask+0: 8(-0.55,-1.7) 9(-0.05,-1.7) 10(0.5,-1.7) 18(0.5,1.7) 19(-0.05,1.7) 20(-0.55,1.7)
  round 0.855 smd paste-1000 mask+0: 21(-0.075,0)
  Top Layer region: -0.55,1 -0.543,1.025 -0.525,1.043 -0.5,1.05 -0.5,1.05 0.099,1.05 0.124,1.044 0.142,1.026 0.149,1.001 0.149,1.001 0.178,0.897 0.252,0.819 0.354,0.785 0.354,0.785 0.377,0.777 0.394,0.759 0.4,0.735 0.4,0.735 0.4,-0.735 0.394,-0.759 0.377,-0.777 0.354,-0.785 0.354,-0.785 0.252,-0.819 0.178,-0.897 0.149,-1.001 0.149,-1.001 0.142,-1.026 0.124,-1.044 0.099,-1.05 0.099,-1.05 -0.249,-1.05 -0.274,-1.044 -0.292,-1.026 -0.299,-1.001 -0.299,-1.001 -0.328,-0.897 -0.402,-0.819 -0.504,-0.785 -0.504,-0.785 -0.527,-0.777 -0.544,-0.759 -0.55,-0.735 -0.55,-0.735
  Top Layer region: 1.45,1.375 1.469,1.379 1.485,1.39 1.496,1.406 1.5,1.425 1.5,1.425 1.5,1.575 1.496,1.594 1.485,1.61 1.469,1.621 1.45,1.625 1.45,1.625 1.275,1.625 1.237,1.633 1.204,1.654 1.183,1.687 1.175,1.725 1.175,1.725 1.175,1.95 1.171,1.969 1.16,1.985 1.144,1.996 1.125,2 1.125,2 0.975,2 0.956,1.996 0.94,1.985 0.929,1.969 0.925,1.95 0.925,1.95 0.925,1.425 0.929,1.406 0.94,1.39 0.956,1.379 0.975,1.375 0.975,1.375
  Top Layer region: 1.45,-1.375 1.469,-1.379 1.485,-1.39 1.496,-1.406 1.5,-1.425 1.5,-1.425 1.5,-1.575 1.496,-1.594 1.485,-1.61 1.469,-1.621 1.45,-1.625 1.45,-1.625 1.275,-1.625 1.237,-1.633 1.204,-1.654 1.183,-1.687 1.175,-1.725 1.175,-1.725 1.175,-1.95 1.171,-1.969 1.16,-1.985 1.144,-1.996 1.125,-2 1.125,-2 0.975,-2 0.956,-1.996 0.94,-1.985 0.929,-1.969 0.925,-1.95 0.925,-1.95 0.925,-1.425 0.929,-1.406 0.94,-1.39 0.956,-1.379 0.975,-1.375 0.975,-1.375
  Top Layer region: -1.45,-1.375 -1.469,-1.379 -1.485,-1.39 -1.496,-1.406 -1.5,-1.425 -1.5,-1.425 -1.5,-1.575 -1.496,-1.594 -1.485,-1.61 -1.469,-1.621 -1.45,-1.625 -1.45,-1.625 -1.275,-1.625 -1.237,-1.633 -1.204,-1.654 -1.183,-1.687 -1.175,-1.725 -1.175,-1.725 -1.175,-1.95 -1.171,-1.969 -1.16,-1.985 -1.144,-1.996 -1.125,-2 -1.125,-2 -0.975,-2 -0.956,-1.996 -0.94,-1.985 -0.929,-1.969 -0.925,-1.95 -0.925,-1.95 -0.925,-1.425 -0.929,-1.406 -0.94,-1.39 -0.956,-1.379 -0.975,-1.375 -0.975,-1.375
  Top Layer region: -1.45,1.375 -1.469,1.379 -1.485,1.39 -1.496,1.406 -1.5,1.425 -1.5,1.425 -1.5,1.575 -1.493,1.6 -1.475,1.618 -1.45,1.625 -1.45,1.625 -1.275,1.625 -1.237,1.633 -1.204,1.654 -1.183,1.687 -1.175,1.725 -1.175,1.725 -1.175,1.95 -1.168,1.975 -1.15,1.993 -1.125,2 -1.125,2 -0.975,2 -0.956,1.996 -0.94,1.985 -0.929,1.969 -0.925,1.95 -0.925,1.95 -0.925,1.425 -0.929,1.406 -0.94,1.39 -0.956,1.379 -0.975,1.375 -0.975,1.375
  silkscreen extent -2.17,-2.22 1.73,2.22, body extent -1.6,-2.1 1.6,2.1, height 0.25
SMA [mm] "Molded Diode, 2-Leads, Body 4.3x2.6mm, IPC Medium Density, based on OnSemi component dimensions and land pattern"
  rect 2x2 smd: 1(-2,0) 2(2,0)
  silkscreen extent -3.66,-1.57 2.79,1.57, body extent -2.6,-1.3 2.6,1.3, height 2.42
SMB [mm] "Molded Diode, 2-Leads, Body 5.4x3.6mm, IPC Medium Density, based on OnSemi component dimensions"
  rect 2.159x2.743 smd: 1(-2.21,0) 2(2.21,0)
  silkscreen extent -3.94,-2.08 3.18,2.08, body extent -2.7,-1.8 2.7,1.8, height 2.32
SOD-323 [mm] "NXP recommended land pattern"
  rect 0.6x0.6 smd paste-0.05: 1(-1.1,0) 2(1.1,0)
  silkscreen extent -2.06,-0.86 1.53,0.86, body extent -1.3,-0.67 1.3,0.68, height 1.1
SOT-23 [mm] "SOT23, 3-Leads, Body 2.9x1.3mm, Pitch 0.95mm, Lead Span 2.5mm, IPC Medium Density"
  rrect50% 1x0.6 smd: 1(-1.2,0.95) 2(-1.2,-0.95) 3(1.2,0)
  silkscreen extent -1.62,-1.5 0.7,1.5, body extent -1.16,-1.45 1.21,1.45, height 1
TE_5-146278-2 [mm] "TE CONNECTIVITY"
  rect 1.65x1.65 hole 1: 1(-1.27,0)
  round 1.65 hole 1: 2(1.27,0)
  silkscreen extent -2.92,-1.27 2.54,1.27, body extent -2.41,-1.17 2.41,1.17, height 8.13
TE_5-146278-3 [mm] "TE CONNECTIVITY"
  rect 1.65x1.65 hole 1: 1(-2.54,0)
  round 1.65 hole 1: 2(0,0) 3(2.54,0)
  silkscreen extent -4.19,-1.27 3.81,1.27, body extent -3.68,-1.17 3.68,1.17, height 8.13
TSW-104-07-G-D [mm] "Samtec 100mil, 2x4, 230 mil above insulator"
  rrect6% 1.65x1.65 hole 1.016: 1(-3.81,-1.27)
  round 1.65 hole 1.016: 2(-3.81,1.27) 3(-1.27,-1.27) 4(-1.27,1.27) 5(1.27,-1.27) 6(1.27,1.27) 7(3.81,-1.27) 8(3.81,1.27)
  silkscreen extent -6.1,-2.54 5.08,2.54, body extent -5.08,-2.54 5.08,2.54, height 8.38
WEEE_Minimum [mm] "WEEElie bin"
  silkscreen extent -2.42,-4.38 2.52,2.65

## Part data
1: library part CMP-0074847-1, "FCC_disclaimer"
C1 C2 C4 C5 C8 C9 C12 C13 C24 C30: library part CMP-0081011-1, "CAP, CERM, 0.1 µF, 100 V,+/- 10%, X7R, AEC-Q200 Grade 1, 0603", Cap_Case=0603, Manufacturer="Taiyo Yuden", Supplier Part Number 1=587-6009-1-ND, TempCo=X7R, Tolerance_%=10%, Value2=100V, ValueDisplayed=0.1µF
C3: library part CMP-0007469-4, "CAP, CERM, 0.1 uF, 100 V, +/- 10%, X7R, 0603", Cap_Case=0603, Manufacturer=MuRata, Supplier Part Number 1=490-3285-1-ND, TempCo=X7R, Tolerance_%=10%, Value1=Unknown, Value2=100V, ValueDisplayed=0.1uF
C6: library part CMP-0079095-1, "CAP, CERM, 0.1 µF, 50 V,+/- 10%, X7R, AEC-Q200 Grade 1, 0603", Cap_Case=0603, Manufacturer=AVX, Supplier Part Number 1=478-3540-1-ND, TempCo=X7R, Tolerance_%=10%, Value2=50V, ValueDisplayed=0.1µF
C7: library part CMP-0086419-1, "Cap Ceramic 0.015uF 50V X7R 10% Pad SMD 0603 125°C T/R", Manufacturer=Kemet, TempCo=15%, Tolerance_%=10%
C10 C11 C14 C15: library part CMP-0006861-3, "CAP, CERM, 0.1 uF, 50 V, +/- 10%, X7R, 0603", Cap_Case=0603, Manufacturer=Kemet, Supplier Part Number 1=399-5089-1-ND, TempCo=X7R, Tolerance_%=10%, Value1=Unknown, Value2=50V, ValueDisplayed=0.1uF
C16: library part CMP-0007542-1, "CAP, CERM, 0.01 uF, 100 V, +/- 5%, X7R, 0805", Cap_Case=0805, Manufacturer=AVX, Supplier Part Number 1=478-3745-1-ND, TempCo=X7R, Tolerance_%=5%, Value1="0.078 ohm", Value2=100V, ValueDisplayed=0.01uF
C17: library part CMP-0006295-2, "CAP, CERM, 0.1 uF, 25 V, +/- 20%, X7R, 0402", Cap_Case=0402, Manufacturer=TDK, PartNumber=C1005X7R1E104M050BB, Supplier Part Number 1=445-7349-1-ND, TempCo=X7R, Tolerance_%=20%, Value1=Unknown, Value2=25V, ValueDisplayed=0.1uF
C18 C19 C20 C21 C25 C26 C27 C28: library part CMP-0096278-1, "Chip Multilayer Ceramic Capacitor for General Purpose 2.2uF ±20% 100V X7T SMD 0805", Digikey Part Number=490-GRM21BD72A225ME01KCT-ND, Manufacturer=Murata, Mouser Part Number=81-GRM21BD72A225ME1K, Operating Temperature Range="-55°C to +125°C", TempCo=+22/-33%, Temperature Characteristic=X7T, Tolerance_%=20%, ValueDisplayed=2.2uF
C22: library part CMP-0097369-1, "Cap Ceramic 22uF 50V X7R 20% SMD 2220 125°C T/R", Digikey Part Number=445-181650-1-ND, Manufacturer=TDK, Mouser Part Number=810-CGA9P3X7R1H226M2, Operating Temperature Range="-55°C to +125°C", TempCo=15%, Temperature Characteristic=X7R, Tolerance_%=20%, ValueDisplayed=22uF
C23 C29: library part CMP-0089881-1, "4.7µF ±10% 100V Ceramic Capacitor X7S 1206 (3216 Metric)", Digikey Part Number=490-18620-1-ND, Manufacturer=Murata, Mouser Part Number=81-GRM31CC72A475KE1L, Operating Temperature Range="-55°C to +125°C", TempCo=22%, Temperature Characteristic=X7S, Tolerance_%=10%, ValueDisplayed=4.7uF
C31: library part CMP-0095369-1, "Cap Ceramic 1uF 16V X7R 20% Pad SMD 0603 +125°C Automotive T/R", Manufacturer=TDK, Operating Temperature Range="-55°C to +125°C", Part Number=CGA3E1X7R1C105M080AC, TempCo=0.15, Temperature Characteristic=X7R, Tolerance_%=0.2%, ValueDisplayed=1uF
C32 C33 C34 C36: library part CMP-0096021-1, "10 µF ±10% 100V Ceramic Capacitor X7R 1210 (3225 Metric)", Digikey Part Number=445-C3225X7R2A106K250ACCT-ND, Manufacturer=TDK, Mouser Part Number=810-C3225X7R2A106K25, Operating Temperature Range="-55°C to +125°C", TempCo=15%, Temperature Characteristic=X7R, Tolerance_%=10%, ValueDisplayed=10uF
C35: library part CMP-0096021-1, "DNP", Digikey Part Number=445-C3225X7R2A106K250ACCT-ND, Manufacturer=TDK, Mouser Part Number=810-C3225X7R2A106K25, Operating Temperature Range="-55°C to +125°C", TempCo=15%, Temperature Characteristic=X7R, Tolerance_%=10%
C37: library part Capacitor, "CAP, CERM, xxxF, xxV, [TempCo], xx%, [PackageReference]", Alternate Manufacturer=-
C38 C39: library part CMP-0006839-2, "DNP", Cap_Case=0603, Manufacturer=Kemet, Supplier Part Number 1=399-1049-1-ND, TempCo=C0G/NP0, Tolerance_%=5%, Value1=Unknown, Value2=50V
D1: library part CMP-0079597-2, "Diode, Switching, 75 V, 0.15 A, AEC-Q101, SOD-323", Manufacturer="Diodes Inc.", Value1=0.15A, Value2=1.25V
D2: library part CMP-0029023-2, "Diode, Superfast Rectifier, SMA"
D3: library part CMP-0028759-3, "Diode, Schottky, 100 V, 20 A, DDPAK", Manufacturer="ON Semiconductor", Value1=20A, Value2=0.8V
D4: library part CMP-0005614-1, "Diode, Zener, 75 V, 550 mW, SMB", Manufacturer="ON Semiconductor", Power_W=550mW, Supplier Part Number 1=10N9668, Value1=0.55W
HT1: library part CMP-0074837-1, "IEC 61010-1 Hot Surface Warning"
J1 J2 J3 J4: library part CMP-0054951-1, "Header, 100mil, 3x1, Tin, TH", Manufacturer="TE Connectivity", Supplier Part Number 1=5-146278-3-ND
J5 J11: library part CMP-0075408-2, "Header, 100mil, 4x2, Gold, TH", Color=Black, Current_A=6.3A, Manufacturer=Samtec, Supplier Part Number 1=SAM1028-04-ND, Voltage_V=550V
J6 J7 J8: library part CMP-0054952-1, "Header, 100mil, 2x1, Tin, TH", Manufacturer="TE Connectivity", Supplier Part Number 1=5-146278-2-ND
J9 J10: library part CMP-0055471-1, "Terminal Block, 5.08 mm, 2x1, TH", Color=Green, Current_A=17.5A, Manufacturer="Phoenix Contact", Supplier Part Number 1=277-1263-ND, Voltage_V=400V
L1: library part CMP-0003374-1, "Ferrite Bead, 600 ohm @ 100 MHz, 3 A, 1210", Manufacturer="Taiyo Yuden", Supplier Part Number 1=587-1755-1-ND, Value1="0.042 ohm", Value2=3A, ValueDisplayed="600 ohm"
L2: library part CMP-0092596-1, "Shielded Power Inductors 1.5 µH 10.2A 10.5mOhm Max Nonstandard", Digikey Part Number=2457-XGL4030-152MEC-ND, Manufacturer=Coilcraft, Operating Temperature Range=to, Self Resonant Frequency=50MHz, Test Frequency=1MHz, Tolerance_%=20%
L3: library part CMP-0043075-1, "1.8 µH Shielded Molded Inductor", Digikey Part Number=2457-XGL6060-182MEC-ND, Manufacturer=Coilcraft, Operating Temperature Range=to, Self Resonant Frequency=35MHz, Supplier Part Number 1=2457-XGL6060-222MEC-ND, Test Frequency=1MHz, Tolerance_%=20%
Q1: library part CMP-0000139-1, "MOSFET, P-CH, -100 V, -15 A, AEC-Q101, DPAK", Alternate Manufacturer=None, Manufacturer="Infineon Technologies", Supplier Part Number 1=SPD15P10PLGBTMA1CT-ND, Value1=0.2, Value2="47 nC"
Q2 Q3: library part CMP-0090058-1, "N-Channel 80V 126A (Tc) 125W (Tc) Surface Mount 8-PQFN (5x6), Power56", Digikey Part Number=NTMFS08N004C-ND, Drain To Source Breakdown Voltage=80V, Input Capacitace At Vds="3035pF @ 40V", Manufacturer="ON Semiconductor", Mouser Part Number=512-NTMFS08N004C, Operating Temperature Range="-55°C to +150°C", Power_W=2.5W, Pulse Drain Current=637A, Typ Forward Diode Voltage=0.7V
Q4: library part CMP-0000366-2, "Transistor, PNP, 100 V, 0.2 A, SOT-23", Manufacturer="Fairchild Semiconductor", Supplier Part Number 1=BSS63CT-ND, Value1="0.2 A"
R1 R2 R3 R11 R12 R14 R15 R18 R19 R22 R23 R31 R32 R33 R38 R39 R41 R43 R45 R50 R51 R53 R55 R64: library part CMP-0023343-3, "RES, 0, 1%, 0.1 W, AEC-Q200 Grade 0, 0603", Manufacturer="Stackpole Electronics Inc", Power_W=100mW, Supplier Part Number 1=RMCF0603ZT0R00CT-ND, TempCo=ppm/C, Tolerance_%=1%, Value2=0.1W, Value_Code=0
R4 R7 R9 R20 R21: library part CMP-0023343-3, "RES, 0, 1%, 0.1 W, AEC-Q200 Grade 0, 0603", Manufacturer="Stackpole Electronics Inc", PartNumber=TBD, Power_W=100mW, TempCo=ppm/C, Tolerance_%=1%, Value2=0.1W, Value_Code=0
R5 R6 R16 R17 R37 R47 R54 R62 R63 R65 R67 R69 R71 R72: library part CMP-0023343-3, "DNP", Manufacturer="Stackpole Electronics Inc", Power_W=100mW, TempCo=ppm/C, Tolerance_%=1%, Value2=0.1W, Value_Code=0
R8 R10 R13 R25 R26 R60: library part CMP-0021998-4, "RES, 10.0 k, 1%, 0.1 W, AEC-Q200 Grade 0, 0603", Manufacturer=Vishay-Dale, Power_W=100mW, Supplier Part Number 1=541-10.0KHCT-ND, TempCo="100 ppm/C", Tolerance_%=1%, Value2=0.1W, Value_Code=10k0, ValueDisplayed=10.0k
R24 R28 R29 R36 R40: library part CMP-0089632-1, "0 Ohms Jumper 0.125W, 1/8W Chip Resistor 0805 (2012 Metric) Automotive AEC-Q200 Thick Film", Digikey Part Number=RMCF0805ZT0R00CT-ND, Manufacturer="Stackpole Electronics", Operating Temperature Range="-55°C to +155°C", Power_W=125mW, TempCo=200ppm/°C
R27: library part CMP-0020835-1, "RES, 100, 1%, 0.125 W, 0805", Manufacturer=Vishay-Dale, Power_W=125mW, Supplier Part Number 1=541-100CCT-ND, TempCo="100 ppm/C", Tolerance_%=1%, Value2=0.125W, Value_Code=100R, ValueDisplayed=100
R30 R35 R42: library part CMP-0021990-1, "RES, 100 k, 1%, 0.1 W, 0603", Manufacturer=Vishay-Dale, Power_W=100mW, Supplier Part Number 1=541-100KHCT-ND, TempCo="100 ppm/C", Tolerance_%=1%, Value2=0.1W, Value_Code=100k
R34: library part CMP-0022377-4, "RES, 3.48 k, 1%, 0.1 W, AEC-Q200 Grade 0, 0603", Manufacturer=Vishay-Dale, Power_W=100mW, Supplier Part Number 1=541-3.48KHCT-ND, TempCo="100 ppm/C", Tolerance_%=1%, Value2=0.1W, Value_Code=3k48, ValueDisplayed=3.48k
R44 R46 R49: library part CMP-0094724-1, "Jumper 0.25W, 1/4W Chip Resistor 1206 (3216 Metric) - Thick Film", Digikey Part Number=541-4170-1-ND, Manufacturer=Vishay, Mouser Part Number=71-CRCW12060000Z0EAC, Operating Temperature Range="-55°C to +155°C", Power_W=250mW
R48: library part CMP-0018318-2, "RES, 47.0 k, 1%, 0.25 W, 1206", Manufacturer="Yageo America", Power_W=250mW, Supplier Part Number 1=311-47.0KFRCT-ND, TempCo="100 ppm/C", Tolerance_%=1%, Value2=0.25W, Value_Code=47k0, ValueDisplayed=47.0k
R52: library part CMP-0020797-2, "RES, 1.0, 5%, 0.4 W, AEC-Q200 Grade 0, 0805", Manufacturer=Rohm, Power_W=400mW, Supplier Part Number 1=RHM1KCT-ND, TempCo="200 ppm/C", Tolerance_%=5%, Value2=0.4W, Value_Code=1R00, ValueDisplayed=1.0
R56: library part CMP-0022204-1, "RES, 20.0 k, 1%, 0.1 W, 0603", Manufacturer=Vishay-Dale, Power_W=100mW, Supplier Part Number 1=541-20.0KHCT-ND, TempCo="100 ppm/C", Tolerance_%=1%, Value2=0.1W, Value_Code=20k0, ValueDisplayed=20.0k
R57: library part CMP-0022109-2, "RES, 1.00 k, 1%, 0.1 W, 0603", Manufacturer=Vishay-Dale, Power_W=100mW, Supplier Part Number 1=541-1.00KHCT-ND, TempCo="100 ppm/C", Tolerance_%=1%, Value2=0.1W, Value_Code=1k00, ValueDisplayed=1.00k
R58: library part CMP-0018576-1, "RES, 10 k, 5%, 0.25 W, 1206", Manufacturer=Vishay-Dale, Power_W=250mW, Supplier Part Number 1=541-10KECT-ND, TempCo="200 ppm/C", Tolerance_%=5%, Value2=0.25W, Value_Code=10k0, ValueDisplayed=10k
R59: library part CMP-0023343-3, "DNP", Manufacturer="Stackpole Electronics Inc", PartNumber=150k, Power_W=100mW, TempCo=ppm/C, Tolerance_%=1%, Value2=0.1W, Value_Code=0
R61: library part CMP-0080492-1, "RES, 49.9, 1%, 0.1 W, 0603", Manufacturer="TT Electronics/IRC", Power_W=100mW, TempCo="100 ppm/C", Tolerance_%=1%, Value2=0.1W, Value_Code=49R9, ValueDisplayed=49.9
R66: library part CMP-0022458-1, "RES, 4.99 k, 1%, 0.1 W, 0603", Manufacturer=Vishay-Dale, Power_W=100mW, Supplier Part Number 1=541-4.99KHCT-ND, TempCo="100 ppm/C", Tolerance_%=1%, Value2=0.1W, Value_Code=4k99, ValueDisplayed=4.99k
R68: library part CMP-0023343-3, "RES, 0, 1%, 0.1 W, AEC-Q200 Grade 0, 0603", Manufacturer="Stackpole Electronics Inc", PartNumber=RMCF0603ZT0R00, Power_W=100mW, Supplier Part Number 1=RMCF0603ZT0R00CT-ND, TempCo=ppm/C, Tolerance_%=1%, Value2=0.1W, Value_Code=0
R70: library part CMP-0022068-3, "RES, 15.8 k, 1%, 0.1 W, 0603", Manufacturer=Vishay-Dale, Power_W=100mW, Supplier Part Number 1=541-15.8KHCT-ND, TempCo="100 ppm/C", Tolerance_%=1%, Value2=0.1W, Value_Code=15k8, ValueDisplayed=15.8k
TP1 TP2 TP3 TP4 TP8 TP9 TP10 TP11 TP12 TP13: library part CMP-0055140-1, "Test Point, Miniature, Orange, TH", Color=Orange, Manufacturer=Keystone, Supplier Part Number 1=36-5003-ND
TP5 TP6 TP7 TP14 TP15 TP16 TP17 TP18: library part CMP-0055141-1, "Test Point, Miniature, Yellow, TH", Color=Yellow, Manufacturer=Keystone, Supplier Part Number 1=36-5004-ND
TP19 TP38: library part CMP-0055148-2, "Test Point, Multipurpose, Black, TH", Color=Black, Manufacturer="Keystone Electronics", PartNumber=5011, Supplier Part Number 1=36-5011-ND
TP20 TP21 TP22 TP23 TP24 TP25 TP26 TP27 TP28 TP29 TP30 TP31 TP32 TP33 TP34 TP36 TP37 TP39 TP40 TP42 TP43: library part CMP-0055137-2, "Test Point, Miniature, Red, TH", Color=Red, Manufacturer="Keystone Electronics", Supplier Part Number 1=36-5000-ND
TP35 TP41: library part CMP-0055138-2, "Test Point, Miniature, Black, TH", Color=Black, Manufacturer="Keystone Electronics", Supplier Part Number 1=36-5001-ND
U1 U2: library part CMP-0098319-1, "Wide VIN 65 V Dual Channel Overvoltage & Undervoltage (OV & UV) TPS3762D02OVDDFR", Manufacturer="Texas Instruments", Max Supply Voltage=65V, Min Supply Voltage=2.7V, Nominal Supply Current=8.1-31.1uA, Operating Temperature Range="-40°C to +125°C"
U3: library part CMP-0089212-1, "Ideal Diode Controller with Load Dump Protection", Manufacturer="Texas Instruments", Max Supply Voltage=65V, Min Supply Voltage=3V, Nominal Supply Current=428uA, Operating Temperature Range="-40°C to +150°C"
U4: library part CMP-0096221-1, "3.5V to 65V Synchronous Step-Down Voltage Regulator", Manufacturer="Texas Instruments", Operating Temperature Range=to
x1: library part CMP-0074769-1

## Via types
v1: diameter 0.61, hole 0.203, Top Layer to Bottom Layer, tented both sides, 68 vias
v2: diameter 0.61, hole 0.2, Top Layer to Bottom Layer, tented both sides, 49 vias
v3: diameter 1.016, hole 0.457, Top Layer to Bottom Layer, tented both sides, 19 vias
v4: diameter 0.5, hole 0.2, Top Layer to Bottom Layer, 9 vias
v5: diameter 0.406, hole 0.203, Top Layer to Bottom Layer, tented both sides, 9 vias
v6: diameter 0.483, hole 0.203, Top Layer to Bottom Layer, tented both sides, 7 vias
v7: diameter 0.864, hole 0.406, Top Layer to Bottom Layer, tented both sides, 3 vias
v8: diameter 0.457, hole 0.203, Top Layer to Bottom Layer, tented both sides, 1 vias
v9: diameter 0.457, hole 0.229, Top Layer to Bottom Layer, tented both sides, 1 vias
v10: diameter 0.61, hole 0.254, Top Layer to Bottom Layer, tented both sides, 1 vias

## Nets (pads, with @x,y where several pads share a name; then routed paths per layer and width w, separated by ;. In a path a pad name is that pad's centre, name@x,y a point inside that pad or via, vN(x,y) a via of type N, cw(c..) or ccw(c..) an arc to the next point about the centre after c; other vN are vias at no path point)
BIAS: C39.1 R64.2 R65.1 TP29.1 U4.20 | length 23.3
  Top Layer w0.254: C39.1@73.675,21.604 v6(74.977,21.604) 75.351,21.978 U4.20@76.007,21.978
  Top Layer w0.635: R64.2@68.566,21.155 68.723,20.998 69.692,20.998 70.043,20.647 v7(70.105,20.647) ; R64.2@68.566,21.335 68.566,19.822 R65.1@68.591,19.797
  Layer 2 w0.508: v7(70.105,20.647) 73.159,17.593 73.159,11.627 72.075,10.543 TP29.1@72.075,10.13
  Layer 2 w0.635: v7(70.105,20.647) 70.167,20.647 70.323,20.803 73.599,20.803 74.399,21.604 v6(74.977,21.604)
DGate: Q3.4 R28.2 | length 12.6
  Top Layer w0.635: 48.629,20.233 48.776,20.38 49.907,20.38 Q3.4@49.919,20.392
  Bottom Layer w1.016: R28.2@47.72,8.988 47.72,14.499 48.546,15.324 v2(48.546,19.937)
External1: J5.7 TP18.1 | length 4.3
  Top Layer w1.016: J5.7@62.224,42.895 TP18.1@62.224,47.149
External2: J11.7 TP40.1 | length 3.6
  Top Layer w1.016: J11.7@99.011,16.575 99.039,16.547 TP40.1@102.536,16.547 TP40.1@102.564,16.519
FAULT: J5.1 J11.1 R53.1 | length 60.6
  Top Layer w0.635: R53.1@91.776,21.028 v2(94.742,21.028)
  Layer 2 w0.508: v2(94.742,21.028) 94.742,11.447 95.811,10.378 97.589,10.378 97.728,10.239 98.282,9.685 98.42,9.685 99.011,9.093 J11.1@99.011,8.955
  Layer 2 w0.635: J5.1@62.224,35.275 64.956,32.544 90.406,32.544 91.134,31.815 91.134,30.738 94.742,27.13 v2(94.742,21.028)
FB: C38.2 R50.1 R68.2 R69.1 R71.2 | length 6
  Top Layer w0.635: R69.1@72.16,15.731 C38.2@73.675,15.731 75.051,15.731 76.406,15.731 76.641,15.496 R71.2@76.641,15.471 ; R71.2@76.644,15.486 76.644,15.731 R50.1@76.644,16.929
